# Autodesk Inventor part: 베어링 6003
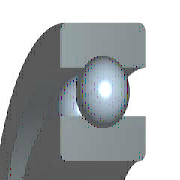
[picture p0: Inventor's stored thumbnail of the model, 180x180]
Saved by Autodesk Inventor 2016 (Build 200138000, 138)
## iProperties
Created: 2012-02
Part Number: 베어링 6003
Material: 강철, 연강
Description: 깊은 그루브 볼 베어링
Document SubType Name: Modeling
Standard: KS B 2023
Designer: mduedu
Standards Organization: KS
Language: ko-KR
Size Designation: 6003 - 17 x 35 x 10
Categories: <MemberInstance><Categories><Category DisplayName="샤프트 부품" InternalName="7f7aeb1f-a693-4053-b835-cee3144e0d98" Mnemonic="SHFT"><Category DisplayName="베어링" Inter
Density: 1 g/cm^3
Appearance: 노란색
IsCustomPart: 1
Author: mduedu
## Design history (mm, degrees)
sketch "스케치" dims "d0" = 4.68 (= -0.26 x WD + 0.26 x BD)
  geometry: L1 (2.66, 13)-(7.34, 13); L2 (5, 13)-(5, 10.66); L3 (5, 13)-(5, 15.34); L4 (3.261, 11.434)-(0, 11.434); L5 (0, 8.5)-(10, 8.5); L6 (3.261, 14.566)-(0, 14.566); L7 (0, 17.5)-(10, 17.5); L8 (10, 8.5)-(10, 11.434); L9 (6.739, 11.434)-(10, 11.434); L10 (6.739, 14.566)-(10, 14.566); L11 (10, 17.5)-(10, 14.566); L12 (-1.4, 0)-(8.4, 0) reference; L13 (0, -0.3)-(0, 5.3) reference
  constraints: 22 end point, 4 point on line, 2 collinear, 2 perpendicular, 2 symmetric about line, 1 midpoint, 1 parallel, 14 other
  dimensions: "d9" = 17 diameter of L5 L12 (= WD); "d11" = 35 diameter of L7 L12 (= BD); "d12" = 10 distance between parallel lines of L8 L13 (= KB); "d13" = 22.868 diameter of L9 L12 (= 0.326 x BD + 0.674 x WD)
revolve "본체" stored, may be unused: angle "d6" = 90 deg
revolve "볼" stored, may be unused: angle "d7" = 90 deg
pattern_circular "IDS_ARRAYBALL[SIMPL:T]" dims angle "d3" = 360 deg
body "Solid1"
fillet "모깎기1" dims "d1" = 0.3 (= KRS)
other parameters: "WD" = 17 [user parameter; used in 5 equation terms], "BD" = 35 [user parameter; used in 5 equation terms], "KB" = 10 [user parameter; used in 1 equation term], "KRS" = 0.3 [user parameter; used in 1 equation term], "d4" = 0, "d5" = 0, "d8" = 0, "d14" = 0, "d15" = 0, "BBA" = 0 [user parameter], "BC0" = 3250000 [user parameter], "BC" = 6050000 [user parameter], "BR" = 17.5 (= 0.5 x BD) [user parameter], "WR" = 8.5 (= 0.5 x WD) [user parameter]
